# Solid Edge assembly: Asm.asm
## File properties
Author: Deepak Maini
Template: Normal.asm
Last saved by: CADCIM
Revision: 8
Application: Solid Edge
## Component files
endplatemod.par
bolt.par
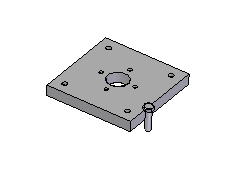
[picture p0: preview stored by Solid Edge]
